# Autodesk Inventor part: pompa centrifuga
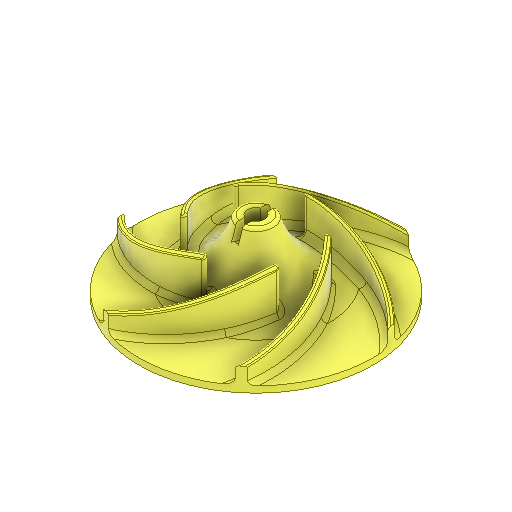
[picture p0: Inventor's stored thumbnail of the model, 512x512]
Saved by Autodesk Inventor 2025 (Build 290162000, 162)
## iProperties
Created: 2024-03
Part Number: pompa centrifuga
Material: Plastica ABS
Document SubType Name: Modeling
Designer: Ryzen5700u
Density: 1.06 g/cm^3
Appearance: Liscia - Giallo
Author: Ryzen5700u
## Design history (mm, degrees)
revolve "Rivoluzione1" stored, may be unused: angle "d7" = 360 deg
sketch "Schizzo10" dims "d78" = 60
  geometry: L1 (0.358, 0.04)-(19.669, 0.04); L2 (0.358, 0.04)-(0.358, 30.043); A1 r 70 centre (0, 0) between (69.365, 9.406) and (34.617, -60.841) reference; A2 r 71.075 centre (17.305, -38.982) between (69.365, 9.406) and (0.358, 30.043); A3 r 74.075 centre (17.305, -38.982) between (68.462, 14.591) and (-0.358, 32.957); A4 r 1.5 centre (0, 31.5) between (-0.358, 32.957) and (0.358, 30.043); 3 further points
  constraints: 9 point on circle, 4 end point, 3 centre point, 2 tangent, 1 coincident, 1 horizontal, 1 vertical, 5 other
  dimensions: "d76" = 3 radial gap between concentric circles of A2 A3
extrude "Estrusione3" join sketch "Schizzo10" stored distance "d29" = 10; taper "d30" = 0 deg
sketch "Schizzo11"
  geometry: L1 (-10, 55)-(10, 55) reference; L2 (-70, 15.8)-(70, 15.8) reference; L3 (70, 15.8)-(70, 25.8); L4 (25.358, 55)-(73.214, 55); L5 (73.214, 55)-(73.214, 15.8); L6 (73.214, 15.8)-(70, 15.8); L7 (0.358, 55)-(25, 55); A1 r 170 centre (139.583, 180.907) between (25.358, 55) and (70, 25.8); 6 further points; 2 other entities
  constraints: 10 end point, 2 perpendicular, 2 point on circle, 2 point on line, 1 centre point, 1 horizontal, 1 vertical, 2 other
  dimensions: "d32" = 10 distance of L2.end L3.end; "d79" = 25 distance of L7.start L4.start
revolve "Rivoluzione3" sketch "Schizzo11" stored, may be unused: angle "d33" = 360 deg
pattern_circular "Serie circolare3" dims "d55" = 360 deg
fillet "Raccordo8" dims "d103" = 1
sketch "Schizzo19"
  geometry: C1 r 11.111 at (0, 0) reference; 2 further points
  constraints: 1 coincident
hole "Foro3" sketch "Schizzo19" at (0, 0) diameter "d104" = 6.6; stored, may be unused: countersink angle "d108" = 90 deg, drill point angle "d110" = 0 deg; dims "d105" = 6, "d106" = 12, "d107" = 4.8, "d109" = 61.1
fillet "Raccordo9" dims "d121" = 3
fillet "Raccordo10" dims "d122" = 0.8
sketch "Schizzo23"
  geometry: C1 r 3.3 at (0, 0) reference; C2 r 6 at (0, 0); 1 further point
  constraints: 1 centre point, 1 coincident
  dimensions: "d126" = 12 diameter of C2
extrude "Estrusione9" cut sketch "Schizzo23" distance "d127" = 35; taper "d128" = 0 deg
node "Piano di lavoro5"
sketch "Schizzo24"
  geometry: L1 (55, 5.1)-(55, -5.1) reference; 2 further points
  dimensions: "d132" = 14 distance from line of L1 point (41, 0)
hole "Foro4" sketch "Schizzo24" diameter "d133" = 3.2; stored, may be unused: countersink angle "d137" = 90 deg, drill point angle "d139" = 118 deg; dims "d134" = 6, "d135" = 6.5, "d136" = 3.4, "d138" = 8
hole "Foro5" sketch "Schizzo24" diameter "d140" = 3.2; stored, may be unused: countersink angle "d144" = 90 deg, drill point angle "d146" = 118 deg; dims "d141" = 6, "d142" = 4, "d143" = 2, "d145" = 8
node "Piano di lavoro6"
node "Asse di lavoro1"
sketch "Schizzo25"
  geometry: 2 further points
hole "Foro6" sketch "Schizzo25" at (42, 0) diameter "d148" = 6.4; stored, may be unused: countersink angle "d152" = 90 deg, drill point angle "d154" = 118 deg; dims "d149" = 6, "d150" = 10, "d151" = 9, "d153" = 8
mirror "Speculare1"
sketch "Schizzo26"
  geometry: L1 (-10, 55)-(10, 55) reference; L2 (1.609, 63.237)-(0, 55); L3 (-10, 55)-(0, 55); L4 (-5.1, 55)-(5.1, 55) reference; L5 (-5.1, 12)-(-5.1, 55) reference; L6 (-5.1, 55)-(1, 60.119); L7 (-5.1, 55)-(2.863, 55); A1 r 44 centre (-53.081, 63.943) between (-43.832, 20.927) and (-10, 55) reference; A2 r 20.937 centre (1.915, 37.784) between (-5.682, 57.294) and (-10, 55); A3 r 8.44 centre (2.391, 54.833) between (1.609, 63.237) and (-5.682, 57.294); 1 further point
  constraints: 8 end point, 4 point on circle, 2 centre point, 1 collinear, 1 equal length, 1 horizontal, 1 midpoint, 1 point on line
  dimensions: "d155" = 40 deg angle of L7 L6
revolve "Rivoluzione7" sketch "Schizzo26" stored, may be unused: angle "d156" = 90 deg
fillet "Raccordo11" dims "d157" = 10
node "Modifica diretta2"
fillet "Raccordo12" dims "d162" = 1
sketch "Schizzo27"
  geometry: L1 (1, 6.245)-(-1, 6.245); L2 (-1, 6.245)-(-1, -6.245); L3 (-1, -6.245)-(1, -6.245); L4 (1, -6.245)-(1, 6.245); L5 (1, 6.245)-(-1, -6.245); L6 (-1, 6.245)-(1, -6.245); 1 further point
  constraints: 12 end point, 2 midpoint, 2 parallel, 1 horizontal, 1 perpendicular
  dimensions: "d163" = 2 distance of L3.end L2.end
extrude "Estrusione10" cut sketch "Schizzo27" distance "d164" = 5; taper "d165" = 0 deg
node "Solido1"
sketch "Schizzo1"
  geometry: L1 (70, 12)-(70, 15.8); L2 (0, 0)-(0, 55); L3 (0, 55)-(10, 55); L4 (5.1, 55)-(5.1, 0); L5 (18, 12)-(35, 12); L6 (50, 15)-(50, 15); L7 (45, 12)-(70, 12); L8 (45, 12)-(0, 12); A1 r 120 centre (102.639, 131.276) between (10, 55) and (70, 15.8); A2 r 44 centre (53.081, 63.943) between (10, 55) and (43.832, 20.927); A3 r 726.984 centre (196.662, 731.665) between (43.832, 20.927) and (70, 15.8); 3 further points
  constraints: 16 end point, 6 point on circle, 4 point on line, 3 centre point, 3 perpendicular, 1 tangent, 1 vertical
  dimensions: "d4" = 10 distance of L2.end L3.end; "d6" = 5.1 distance between parallel lines of L2 L4; "d80" = 44 radius of A2; "d123" = 43 distance between parallel lines of L8 L3; "d124" = 3.8 distance of L1.start L1.end; "d125" = 70 distance between parallel lines of L2 L1; "d161" = 12 distance from line of L2.start L8
feature "Scala2"
other parameters: "d131" = 225 deg, "d147" = -25, "d158" = 5
